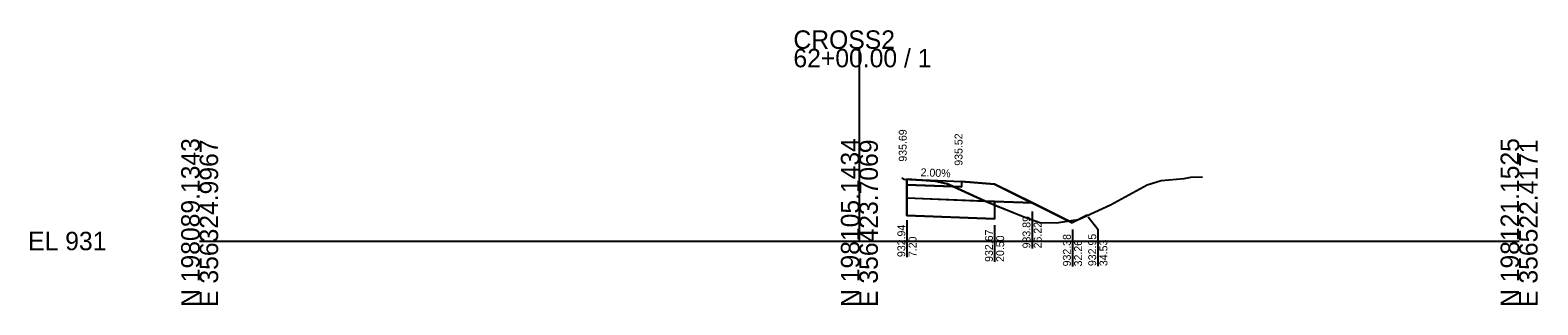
# Model space of a CAD drawing. Extents: x -26 to 203, y -10 to 14021.
# Drawn here: x -25.7 to 202.8, y 2990.3 to 3032 of the extents above; entities that cross this region are included whole.
import ezdxf

# ---------------------------------------------------------------- set-up
doc = ezdxf.new("R2010")
doc.units = 0
for name, color, linetype in [('Default', 7, 'Continuous'), ('P_E_XS_Ground', 7, 'Continuous'), ('P_XS', 7, 'Continuous'), ('P_XS_EAR_CommonGrnd', 7, 'Continuous'), ('P_XS_Lane', 7, 'Continuous'), ('P_XS_Rock', 7, 'Continuous')]:
    doc.layers.add(name, color=color, linetype=linetype)

msp = doc.modelspace()

# ---------------------------------------------------------------- linework, layer by layer
at = {"layer": 'Default'}
for p, q in [((100, 3000), (100, 3029.16)), ((0, 3000), (100, 3000)), ((100, 3000), (200, 3000))]:
    msp.add_line(p, q, dxfattribs=at)
at = {"layer": 'P_E_XS_Ground'}
for p, q in [((106.42, 3009.57), (106.81, 3009.4)), ((106.81, 3009.4), (109.4, 3009.24)), ((109.4, 3009.24), (111.48, 3009.08)), ((111.48, 3009.08), (113.33, 3008.69)), ((113.33, 3008.69), (113.67, 3008.5)), ((113.67, 3008.5), (120.07, 3005.62)), ((138.04, 3005.51), (143.61, 3008.54)), ((143.61, 3008.54), (145.73, 3009.17)), ((145.73, 3009.17), (149.22, 3009.48)), ((149.22, 3009.48), (150.26, 3009.68)), ((150.26, 3009.68), (152.03, 3009.72)), ((120.07, 3005.62), (120.42, 3005.5)), ((120.42, 3005.5), (125.07, 3003.6)), ((133.2, 3003.28), (138.04, 3005.51)), ((125.07, 3003.6), (127.34, 3002.82)), ((129.87, 3002.76), (133.2, 3003.28)), ((127.34, 3002.82), (129.87, 3002.76))]:
    msp.add_line(p, q, dxfattribs=at)
at = {"layer": 'P_XS'}
for p, q in [((107.2, 3009.38), (107.2, 3008.54)), ((107.2, 3008.54), (115.5, 3008.21)), ((107.2, 3006.54), (107.2, 3008.54)), ((115.5, 3009.04), (115.5, 3008.21)), ((107.2, 3006.54), (126.22, 3005.78)), ((107.2, 3006.54), (107.2, 3003.87)), ((120.5, 3006.01), (120.5, 3003.34)), ((107.2, 3003.87), (120.5, 3003.34))]:
    msp.add_line(p, q, dxfattribs=at)
at = {"layer": 'P_XS_EAR_CommonGrnd'}
for points in [[(109.4, 3009.24), (111.48, 3009.08), (113.33, 3008.69), (113.67, 3008.5), (114.21, 3008.26), (107.2, 3008.54), (107.2, 3009.38)], [(115.5, 3009.04), (115.5, 3008.21), (114.21, 3008.26), (113.67, 3008.5), (113.33, 3008.69), (111.48, 3009.08), (109.4, 3009.24), (107.2, 3009.38)], [(107.2, 3006.54), (119.08, 3006.07), (114.21, 3008.26), (107.2, 3008.54)], [(115.5, 3009.04), (115.5, 3008.21), (114.21, 3008.26), (119.08, 3006.07), (120.5, 3006.01), (126.22, 3005.78), (120.5, 3008.64)], [(120.42, 3005.5), (120.5, 3005.47), (120.5, 3003.34), (107.2, 3003.87), (107.2, 3006.54), (119.08, 3006.07), (120.07, 3005.62)], [(120.42, 3005.5), (120.5, 3005.47), (120.5, 3006.01), (119.08, 3006.07), (120.07, 3005.62)], [(120.5, 3005.47), (125.07, 3003.6), (127.34, 3002.82), (129.87, 3002.76), (131.69, 3003.05), (126.22, 3005.78), (120.5, 3006.01)], [(133.2, 3003.28), (134.53, 3003.9), (132.26, 3002.76), (131.69, 3003.05)]]:
    msp.add_lwpolyline(points, close=True, dxfattribs=at)
at = {"layer": 'P_XS_Lane'}
for p, q in [((107.2, 3009.38), (115.5, 3009.04)), ((115.5, 3009.04), (120.5, 3008.64)), ((120.5, 3008.64), (132.26, 3002.76)), ((134.53, 3003.9), (132.26, 3002.76))]:
    msp.add_line(p, q, dxfattribs=at)
at = {"layer": 'P_XS_Rock'}
for p, q in [((107.21, 3003.17), (107.21, 2997.55)), ((126.18, 3004.47), (126.18, 2998.87)), ((134.69, 3003.69), (136.14, 3001.8)), ((120.49, 3002.42), (120.49, 2996.82)), ((132.3, 3001.75), (132.3, 2996.15)), ((136.14, 3001.8), (136.14, 2996.19))]:
    msp.add_line(p, q, dxfattribs=at)

# ---------------------------------------------------------------- texts
at = {"layer": 'Default'}
for s, p in [('CROSS2', (90, 3029.16)), ('62+00.00 / 1', (90, 3026.36)), ('EL 931', (-26, 2998.6))]:
    msp.add_text(s, height=2.8, dxfattribs=at).set_placement(p)
for s, p in [('N 198089.1343', (0, 2990)), ('E 356324.9967', (2.8, 2990)), ('N 198105.1434', (100, 2990)), ('E 356423.7069', (102.8, 2990)), ('N 198121.1525', (200, 2990)), ('E 356522.4171', (202.8, 2990))]:
    msp.add_text(s, height=2.8, rotation=90, dxfattribs=at).set_placement(p)
at = {"layer": 'P_XS_Rock'}
for s, rotation, p in [('935.69', 90, (107.17, 3012.04)), ('935.52', 90, (115.63, 3011.42)), ('2.00%', 357.7094, (109.26, 3009.84)), ('933.89', 90, (125.93, 2998.88)), ('932.94', 90, (106.96, 2997.56)), ('932.67', 90, (120.24, 2996.83)), ('20.50', 90, (121.94, 2996.83)), ('26.22', 90, (127.63, 2998.88)), ('932.38', 90, (132.05, 2996.15)), ('932.95', 90, (135.89, 2996.19)), ('7.20', 90, (108.66, 2997.56)), ('32.26', 90, (133.75, 2996.15)), ('34.53', 90, (137.59, 2996.19))]:
    msp.add_text(s, height=1.2, rotation=rotation, dxfattribs=at).set_placement(p)

doc.saveas('drawing.dxf')
